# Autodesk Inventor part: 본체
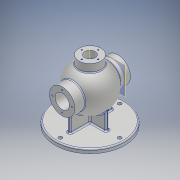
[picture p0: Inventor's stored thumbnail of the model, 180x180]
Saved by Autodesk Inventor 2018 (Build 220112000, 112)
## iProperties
Created: 2020-08
Part Number: 본체
Material: 알루미늄 6061
Document SubType Name: Modeling
Designer: USER
Density: 2.7 g/cm^3
Appearance: 알루미늄 - 평지
Mass: 1753.32 g
Surface Area: 1341.62 cm^2
Volume: 649.377 cm^3
Author: USER
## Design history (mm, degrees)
sketch "스케치1"
  geometry: C1 r 85 at (0, 0); 1 further point
  constraints: 1 centre point, 1 coincident
  dimensions: "d0" = 170 diameter of C1
extrude "돌출1" new body sketch "스케치1" distance "d1" = 10; taper "d2" = 0 deg
sketch "스케치3"
  geometry: L1 (-85, 0)-(85, 0) reference; L2 (0, -40.2)-(0, 241.2) reference; C1 r 31 at (0, 85); 1 further point
  constraints: 1 centre point, 1 point on line
  dimensions: "d10" = 62 diameter of C1; "d11" = 85 distance from line of L1 C1.centre
extrude "돌출2" new body sketch "스케치3" stored distance "d12" = 136; taper "d13" = 0 deg
sketch "스케치6"
  geometry: L1 (-85, 0)-(85, 0) reference; L2 (0, -27.6)-(0, 165.6) reference; C1 r 17.5 at (0, 85); 1 further point
  constraints: 1 centre point, 1 point on line
  dimensions: "d23" = 35 diameter of C1; "d24" = 85 distance from line of L1 C1.centre
extrude "돌출3" join sketch "스케치6" extent not by distance; stored distance "d25" = 136; taper "d26" = 0 deg
sketch "스케치9"
  geometry: L1 (-53, 85)-(53, 85); L2 (-85, 0)-(85, 0) reference; L3 (0, 165.6)-(0, -27.6) reference; A1 r 53 centre (0, 85) between (53, 85) and (-53, 85); 2 further points
  constraints: 2 end point, 2 midpoint, 2 point on circle, 1 centre point, 1 horizontal, 1 point on line
  dimensions: "d32" = 53 radius of A1; "d33" = 85 distance between parallel lines of L2 L1
revolve "회전3" sketch "스케치9" stored, may be unused: angle "d34" = 90 deg
sketch "스케치10"
  geometry: L1 (-43, 85)-(43, 85); L2 (-85, 0)-(85, 0) reference; L3 (0, 165.6)-(0, -27.6) reference; A1 r 43 centre (0, 85) between (43, 85) and (-43, 85); 2 further points
  constraints: 2 end point, 2 midpoint, 2 point on circle, 1 centre point, 1 horizontal, 1 point on line
  dimensions: "d35" = 43 radius of A1; "d36" = 85 distance between parallel lines of L2 L1
revolve "회전4" sketch "스케치10" stored, may be unused: angle "d37" = 90 deg
feature "결합3"
  node "솔리드7"
feature "결합4"
  node "솔리드5"
sketch "스케치13"
  geometry: C1 r 17.5 at (0, 0); C2 r 17.5 at (0, 0) reference; 1 further point
  constraints: 1 centre point, 1 concentric
  dimensions: "d39" = 35 diameter of C1
extrude "돌출5" new body sketch "스케치13" extent not by distance; stored distance "d40" = 1.75; taper "d41" = 0 deg
feature "결합5"
  node "솔리드9"
node "작업 평면2"
sketch "스케치14"
  geometry: C1 r 27 at (0, 0); 1 further point
  constraints: 1 centre point, 1 coincident
  dimensions: "d43" = 54 diameter of C1
extrude "돌출6" new body sketch "스케치14" distance "d44" = 50; taper "d45" = 0 deg
sketch "스케치15"
  geometry: 1 further point
feature "OffsetSrf1" dims "d46" = 0, "d47" = 0
feature "분할1"
feature "분할2"
feature "결합6"
  node "솔리드2"
feature "결합7"
  node "솔리드10"
sketch "스케치17"
  geometry: 2 further points
  constraints: 1 coincident
hole "구멍1" sketch "스케치17" at (0, 0) diameter "d51" = 26; stored, may be unused: countersink angle "d55" = 90 deg, drill point angle "d57" = 0 deg; dims "d52" = 6, "d53" = 4, "d54" = 2, "d56" = 55
sketch "스케치18"
  geometry: L1 (-4, 4)-(-4, 52); L2 (-4, 52)-(4, 52); L3 (4, 52)-(4, 4); L4 (4, 4)-(43, 4); L5 (43, 4)-(43, -4); L6 (43, -4)-(4, -4); L7 (4, -4)-(4, -52); L8 (4, -52)-(-4, -52); L9 (-4, -52)-(-4, -4); L10 (-4, -4)-(-43, -4); L11 (-43, -4)-(-43, 4); L12 (-43, 4)-(-4, 4); L13 (-119, 0)-(119, 0) reference; L14 (0, 119)-(0, -119) reference; 1 further point
  constraints: 24 end point, 10 perpendicular, 2 collinear, 2 point on line, 1 vertical
  dimensions: "d58" = 8 distance between parallel lines of L10 L12; "d59" = 8 distance between parallel lines of L6 L4; "d60" = 8 distance between parallel lines of L3 L1; "d62" = 8 distance between parallel lines of L7 L9; "d63" = 104 distance between parallel lines of L8 L2; "d64" = 86 distance between parallel lines of L5 L11; "d65" = 52 distance between parallel lines of L13 L2 (= 0.5 x d63); "d66" = 43 distance between parallel lines of L14 L5 (= 0.5 x d64); "d67" = 4 distance between parallel lines of L13 L12 (= 0.5 x d59)
extrude "돌출8" join sketch "스케치18" distance "d68" = 50; taper "d69" = 0 deg
feature "OffsetSrf2" dims "d70" = 0, "d71" = 0
feature "분할3"
feature "결합8"
  node "솔리드1"
sketch "스케치19"
  geometry: L1 (0, 35.905)-(0, -24.179); C1 r 17.5 at (0, 0) reference; 2 further points
  constraints: 2 end point, 2 point on line, 1 vertical
  dimensions: "d72" = 24 distance of C1.centre point (0, 24)
hole "구멍2" sketch "스케치19" at (0, 24) diameter "d73" = 3.242; stored, may be unused: countersink angle "d77" = 90 deg, drill point angle "d79" = 118 deg; dims "d74" = 8, "d75" = 9.4, "d76" = 4.775, "d78" = 11.8
sketch "스케치20"
  geometry: L1 (0, 115)-(0, -95) reference; L2 (-119, 85)-(119, 85) reference; C1 r 17.5 at (0, 0) reference; 2 further points
  constraints: 1 point on line
  dimensions: "d83" = 24 distance of C1.centre point (0, -24)
hole "구멍3" sketch "스케치20" at (0, -24) diameter "d84" = 3.242; stored, may be unused: countersink angle "d88" = 90 deg, drill point angle "d90" = 118 deg; dims "d85" = 12, "d86" = 9.4, "d87" = 4.775, "d89" = 15
sketch "스케치21"
  geometry: L1 (-119, 0)-(119, 0) reference; L2 (0, -119)-(0, 119) reference; 2 further points
  constraints: 1 point on line
  dimensions: "d94" = 20 distance from line of L1 point (0, -20)
hole "구멍4" sketch "스케치21" at (0, -20) diameter "d95" = 3.242; stored, may be unused: countersink angle "d99" = 90 deg, drill point angle "d101" = 118 deg; dims "d96" = 12, "d97" = 9.4, "d98" = 4.775, "d100" = 15
fillet "모깎기1" dims "d105" = 3
fillet "모깎기2" dims "d106" = 3
fillet "모깎기3" dims "d107" = 3
fillet "모깎기4" dims "d108" = 3
sketch "스케치22"
  geometry: L1 (-119, 0)-(119, 0) reference; L2 (0, -119)-(0, 119) reference; C1 r 4.5 at (0, -72.5); 1 further point
  constraints: 1 centre point, 1 point on line
  dimensions: "d109" = 9 diameter of C1; "d110" = 72.5 distance from line of L1 C1.centre
extrude "돌출9" cut sketch "스케치22" extent not by distance; stored distance "d111" = 50; taper "d112" = 0 deg
node "작업 평면3"
sketch "스케치23"
  geometry: C1 r 18.5 at (0, 0); 1 further point
  constraints: 1 centre point
  dimensions: "d117" = 37 diameter of C1
extrude "돌출10" new body sketch "스케치23" distance "d118" = 1.75; taper "d119" = 0 deg
feature "결합9"
  node "솔리드12"
pattern_circular "원형 패턴1" dims angle "d81" = 360 deg
pattern_circular "원형 패턴2" dims angle "d92" = 360 deg
pattern_circular "원형 패턴3" dims angle "d103" = 360 deg
pattern_circular "원형 패턴4" dims angle "d114" = 360 deg
node "솔리드8"
body "Srf1"
body "Srf2"
other parameters: "d5" = 62, "d116" = -16
